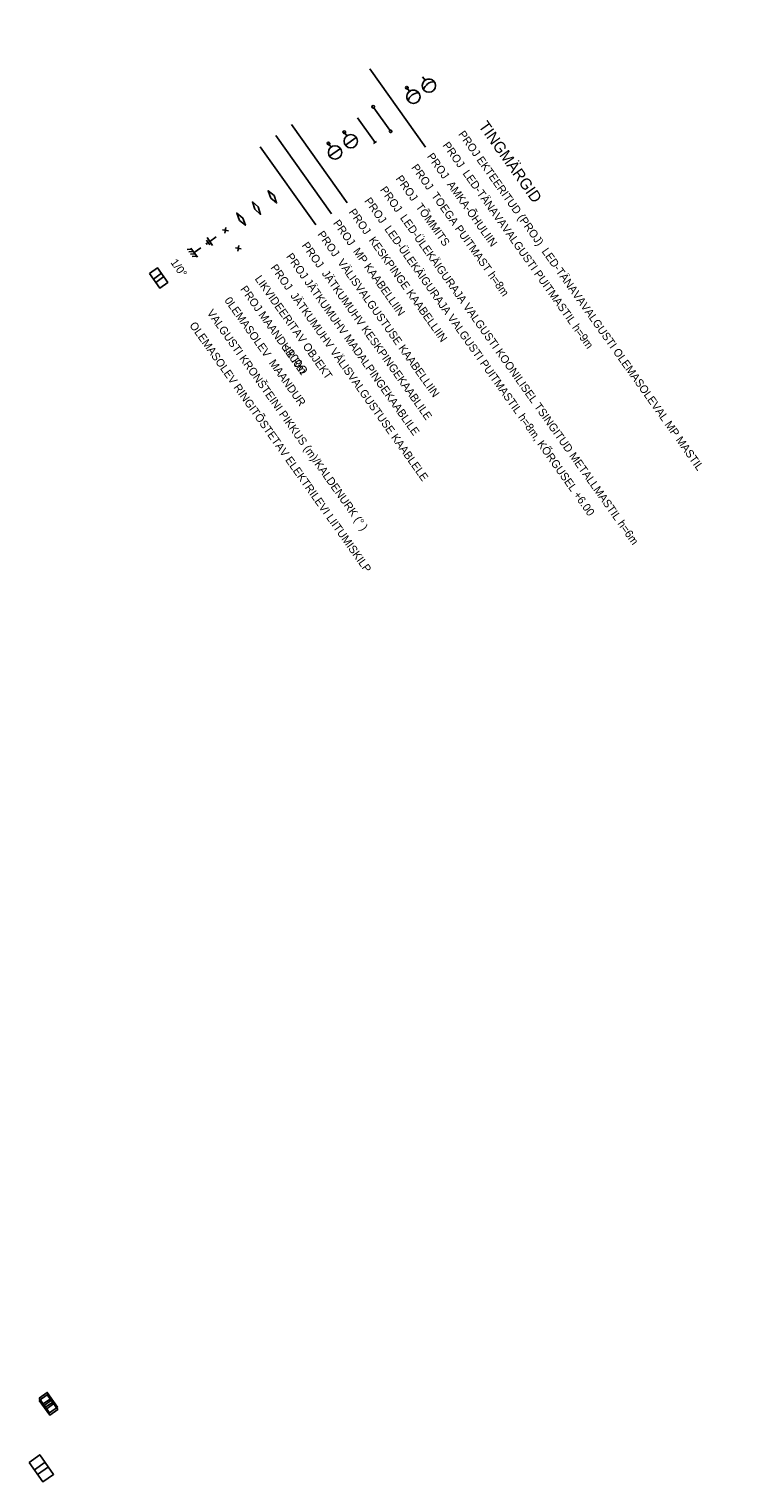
# Model space of a CAD drawing. Extents: x -52238384 to 549205, y 6582846 to 57187752.
# Drawn here: x 539807.1 to 539940.2, y 6582845.9 to 6583118.3 of the extents above; entities that cross this region are included whole.
import ezdxf

# ---------------------------------------------------------------- set-up
doc = ezdxf.new("R2010")
doc.units = 0
for name, color, linetype in [('EL Abi', 7, 'Continuous'), ('EL ELL mp kaabel', 7, 'Continuous'), ('EL Mp AMKA', 7, 'Continuous'), ('EL PrMPkaab', 7, 'Continuous'), ('EL Proj KP kaab', 7, 'Continuous'), ('EL Proj MP VV kaabelliin', 7, 'Continuous'), ('EL Text', 7, 'Continuous'), ('EL Text1', 7, 'Continuous'), ('EL Valgustid', 7, 'Continuous')]:
    doc.layers.add(name, color=color, linetype=linetype)

# ---------------------------------------------------------------- blocks, each defined once
blk = doc.blocks.new('EL DEM')
at = {"layer": 'EL Dem'}
for points in [[(32, -32), (-32, 32)], [(32, 32), (-32, -32)]]:
    blk.add_lwpolyline(points, dxfattribs=at)
blk = doc.blocks.new('EL LED VV')
at = {"layer": 'Tingmärk'}
blk.add_line((-1, 69), (0, 0), dxfattribs=at)
blk.add_circle((-2, 173), 104, dxfattribs=at)
for centre, radius, start, end in [((-4, 312), 173, 233.8435, 307.5833), ((-2, 173), 104, 180.7134, 270.7134), ((-2, 173), 104, 270.7134, 0.7134)]:
    blk.add_arc(centre, radius, start, end, dxfattribs=at)
blk = doc.blocks.new('EL Tõmmits')
at = {"layer": 'EL PrVälVal'}
for points in [[(0, 0), (0, -470)], [(-30, -470), (30, -470)]]:
    blk.add_lwpolyline(points, dxfattribs=at)
blk = doc.blocks.new('EL Proj Maandur')
at = {"layer": 'EL Proj MP VV kaabelliin'}
for points in [[(0, 0), (0, -250)], [(-150, -250), (150, -250)], [(-90, -310), (90, -310)], [(-30, -370), (30, -370)]]:
    blk.add_lwpolyline(points, dxfattribs=at)
blk = doc.blocks.new('EL OLolev maandur')
at = {"layer": 'EL Proj MP VV kaabelliin'}
for points in [[(0, 0), (0, -250)], [(-204, -370), (-135, -250)], [(-175, -250), (175, -250)], [(-114, -370), (-45, -250)], [(-24, -370), (45, -250)], [(66, -370), (135, -250)]]:
    blk.add_lwpolyline(points, dxfattribs=at)
blk = doc.blocks.new('EL Vöötraja valgusti')
at = {"layer": 'EL Valgustid'}
blk.add_lwpolyline([(173, 106), (173, -102)], dxfattribs=at)
at = {"layer": 'Tingmärk'}
blk.add_line((69, 1), (0, 0), dxfattribs=at)
blk.add_circle((173, 2), 104, dxfattribs=at)
blk = doc.blocks.new('EL KP jätkumuhv')
at = {"layer": 'EL Proj KP kaab'}
for p, q in [((0, 0), (-16, -58)), ((16, -58), (0, 0)), ((-16, -58), (0, -116)), ((0, -116), (16, -58))]:
    blk.add_line(p, q, dxfattribs=at)
blk.add_lwpolyline([(-16, -58), (0, -116), (16, -58), (0, 0)], close=True, dxfattribs=at)
blk = doc.blocks.new('EL MP jätkumuhv')
at = {"layer": 'EL Proj KP kaab'}
for p, q in [((58, 14), (0, 0)), ((0, 0), (57, -17)), ((116, -4), (58, 14)), ((57, -17), (116, -4))]:
    blk.add_line(p, q, dxfattribs=at)
blk.add_lwpolyline([(57, -17), (116, -4), (58, 14), (0, 0)], close=True, dxfattribs=at)
blk = doc.blocks.new('Jätkumuhv')
at = {"layer": 'EL ELL mp kaabel'}
for p, q in [((-46.4, 0), (0, 12.4)), ((0, 12.4), (46.4, 0)), ((46.4, 0), (0, -12.4)), ((0, -12.4), (-46.4, 0)), ((0, -12.4), (0, -12.4))]:
    blk.add_line(p, q, dxfattribs=at)
blk.add_lwpolyline([(0, -12.4), (-46.4, 0), (0, 12.4), (46.4, 0), (0, -12.4), (0, -12.4)], close=True, dxfattribs=at)
blk = doc.blocks.new('EL Rimgitõstetav liitumiskilp')
at = {"layer": 'EL PrMPkaab'}
for points in [[(-59.7, 0), (59.7, 0), (59.7, -58.8), (-59.7, -58.8), (-59.7, 0)], [(-13.6, 0), (-13.6, -59.7)], [(13.6, 0), (13.6, -59.7)]]:
    blk.add_lwpolyline(points, dxfattribs=at)
blk = doc.blocks.new('EL Tingmärgid')
at = {"layer": 'EL ELL mp kaabel'}
blk.add_lwpolyline([(-3418, -5319), (-418, -5319)], dxfattribs=at)
at = {"layer": 'EL Mp AMKA'}
for points in [[(-3418, -1719), (-418, -1719)], [(-1488, -2320), (-2348, -2320)]]:
    blk.add_lwpolyline(points, dxfattribs=at)
for centre, start, end in [((-2265, -1119), 106.8332, 286.8332), ((-2265, -1119), 286.8332, 106.8332), ((-2388, -2320), 104.0496, 284.0496), ((-2388, -2320), 284.0496, 104.0496), ((-1448, -2320), 104.0496, 284.0496), ((-1448, -2320), 284.0496, 104.0496), ((-2265, -3519), 104.0496, 284.0496), ((-2265, -3519), 284.0496, 104.0496), ((-2265, -4123), 104.0496, 284.0496), ((-2265, -4123), 284.0496, 104.0496)]:
    blk.add_arc(centre, 40, start, end, dxfattribs=at)
at = {"layer": 'EL Proj KP kaab'}
blk.add_lwpolyline([(-3418, -4719), (-418, -4719)], dxfattribs=at)
at = {"layer": 'EL Proj MP VV kaabelliin'}
blk.add_lwpolyline([(-3418, -5919), (-418, -5919)], dxfattribs=at)
at = {"layer": 'EL Abi', "xscale": 2, "yscale": 2, "rotation": -90.00000000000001}
blk.add_blockref('EL LED VV', (-2265, -523), dxfattribs=at)
at = {"layer": 'EL ELL mp kaabel', "xscale": 4, "yscale": 4}
blk.add_blockref('EL MP jätkumuhv', (-2152, -7119), dxfattribs=at)
at = {"layer": 'EL Mp AMKA', "xscale": 2, "yscale": 2, "rotation": 90}
blk.add_blockref('EL Tõmmits', (-2388, -2919), dxfattribs=at)
at = {"layer": 'EL PrMPkaab', "xscale": 4.999883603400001, "yscale": 4.999883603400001}
blk.add_blockref('Jätkumuhv', (-1918, -7719), dxfattribs=at)
at = {"layer": 'EL Proj KP kaab', "xscale": 3.999999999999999, "yscale": 3.999999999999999, "rotation": 90}
blk.add_blockref('EL KP jätkumuhv', (-2155, -6519), dxfattribs=at)
at = {"layer": 'EL Proj MP VV kaabelliin'}
for name, p in [('EL Proj Maandur', (-1919, -8669)), ('EL OLolev maandur', (-1918, -9269))]:
    blk.add_blockref(name, p, dxfattribs=at)
at = {"layer": 'EL Text', "xscale": 2, "yscale": 2}
for name, p in [('EL Vöötraja valgusti', (-2265, -3519)), ('EL Vöötraja valgusti', (-2265, -4123)), ('EL DEM', (-1918, -8319))]:
    blk.add_blockref(name, p, dxfattribs=at)
at = {"layer": 'EL Text', "xscale": 2, "yscale": -2, "rotation": 180}
blk.add_blockref('EL DEM', (-1227, -8319), dxfattribs=at)
at = {"layer": 'EL Text1', "xscale": 4.709378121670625, "yscale": -5.2189144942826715}
blk.add_blockref('EL Rimgitõstetav liitumiskilp', (-1918, -11036), dxfattribs=at)
at = {"layer": 'EL Valgustid', "xscale": 2, "yscale": 2, "rotation": -90.00000000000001}
blk.add_blockref('EL LED VV', (-2265, -1119), dxfattribs=at)
at = {"layer": 'EL Text'}
for s, height, p in [('TINGMÄRGID', 350, (0, 0)), ('PROJ EKTEERITUD (PROJ)  LED-TÄNAVAVALGUSTI OLEMASOLEVAL MP MASTIL', 250, (-157, -661)), ('PROJ  LED-TÄNAVAVALGUSTI PUITMASTIL h=9m', 250, (-157, -1261)), ('PROJ  AMKA-ÕHULIIN ', 250, (-157, -1861)), ('PROJ  TOEGA PUITMAST h=8m', 250, (-157, -2461)), ('PROJ  TÕMMITS', 250, (-157, -3061)), ('PROJ  LED-ÜLEKÄIGURAJA VALGUSTI KOONILISEL TSINGITUD METALLMASTIL h=6m', 250, (-157, -3661)), ('PROJ  LED-ÜLEKÄIGURAJA VALGUSTI PUITMASTIL h=8m, KÕRGUSEL +6.00', 250, (-157, -4261)), ('PROJ  KESKPINGE KAABELLIIN', 250, (-157, -4861)), ('PROJ  MP KAABELLIIN ', 250, (-157, -5461)), ('PROJ  VÄLISVALGUSTUSE KAABELLIIN', 250, (-157, -6061)), ('PROJ  JÄTKUMUHV KESKPINGEKAABLILE', 250, (-157, -6661)), ('PROJ JÄTKUMUHV MADALPINGEKAABLILE', 250, (-157, -7261)), ('PROJ  JÄTKUMUHV VÄLISVALGUSTUSE KAABLELE', 250, (-157, -7861)), ('LIKVIDEERITAV OBJEKT', 250, (-157, -8461)), ('PROJ MAANDUR Rm', 250, (-157, -9019)), ('≤100Ω', 270.8, (2086, -9019)), ('0LEMASOLEV  MAANDUR', 250, (-157, -9626)), ('VALGUSTI KRONŠTEINI PIKKUS (m)/KALDENURK (° )', 250, (-157, -10297)), ('1/0°', 250, (-2104, -10311)), ('OLEMASOLEV RINGITÕSTETAV ELEKTRILEVI LIITUMISKILP', 250, (-157, -10968))]:
    blk.add_text(s, height=height, dxfattribs=at).set_placement(p)

msp = doc.modelspace()

# ---------------------------------------------------------------- block references
at = {"layer": 'EL Text'}
for p, xscale, yscale, rotation in [((539810.02, 6582860.23), 0.028256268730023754, -0.03131348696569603, -54.58661712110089), ((539808.45, 6582847.73), 0.037675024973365, -0.04175131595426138, -54.5866171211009)]:
    msp.add_blockref('EL Rimgitõstetav liitumiskilp', p, dxfattribs=dict(at, xscale=xscale, yscale=yscale, rotation=rotation))
at = {"layer": 'EL Text1', "rotation": -54.58661712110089}
for name, p, xscale, yscale in [('EL Tingmärgid', (539891.31, 6583100.12), 0.006000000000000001, 0.006), ('EL Rimgitõstetav liitumiskilp', (539810.04, 6582859.82), 0.028256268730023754, -0.03131348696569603)]:
    msp.add_blockref(name, p, dxfattribs=dict(at, xscale=xscale, yscale=yscale))

doc.saveas('drawing.dxf')
